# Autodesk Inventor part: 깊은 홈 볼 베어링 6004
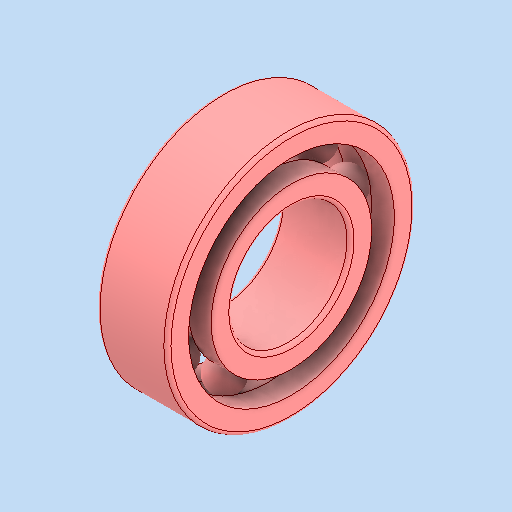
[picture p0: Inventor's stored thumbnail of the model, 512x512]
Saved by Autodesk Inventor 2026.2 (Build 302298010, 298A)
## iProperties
Created: 2026-03
Part Number: 깊은 홈 볼 베어링 6004
Material: 강철, 연강
Description: 깊은 그루브 볼 베어링
Document SubType Name: Modeling
Designer: PC-2-03
Density: 7.85 g/cm^3
Appearance: 기본값
Author: jhkim
Sending System: Autodesk Inventor 2026
Preprocessor: ST-DEVELOPER v20.1
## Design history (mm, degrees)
feature "Solid1"
feature "Solid1:1"
feature "Solid1:2"
feature "Solid1:3"
feature "Solid1:4"
feature "Solid1:5"
feature "Solid1:6"
feature "Solid1:7"
feature "Solid1:8"
feature "Solid1:9"
feature "Solid1:10"
node "솔리드1"
node "솔리드2"
node "솔리드3"
node "솔리드4"
node "솔리드5"
node "솔리드6"
node "솔리드7"
node "솔리드8"
node "솔리드9"
node "솔리드10"
node "솔리드11"
